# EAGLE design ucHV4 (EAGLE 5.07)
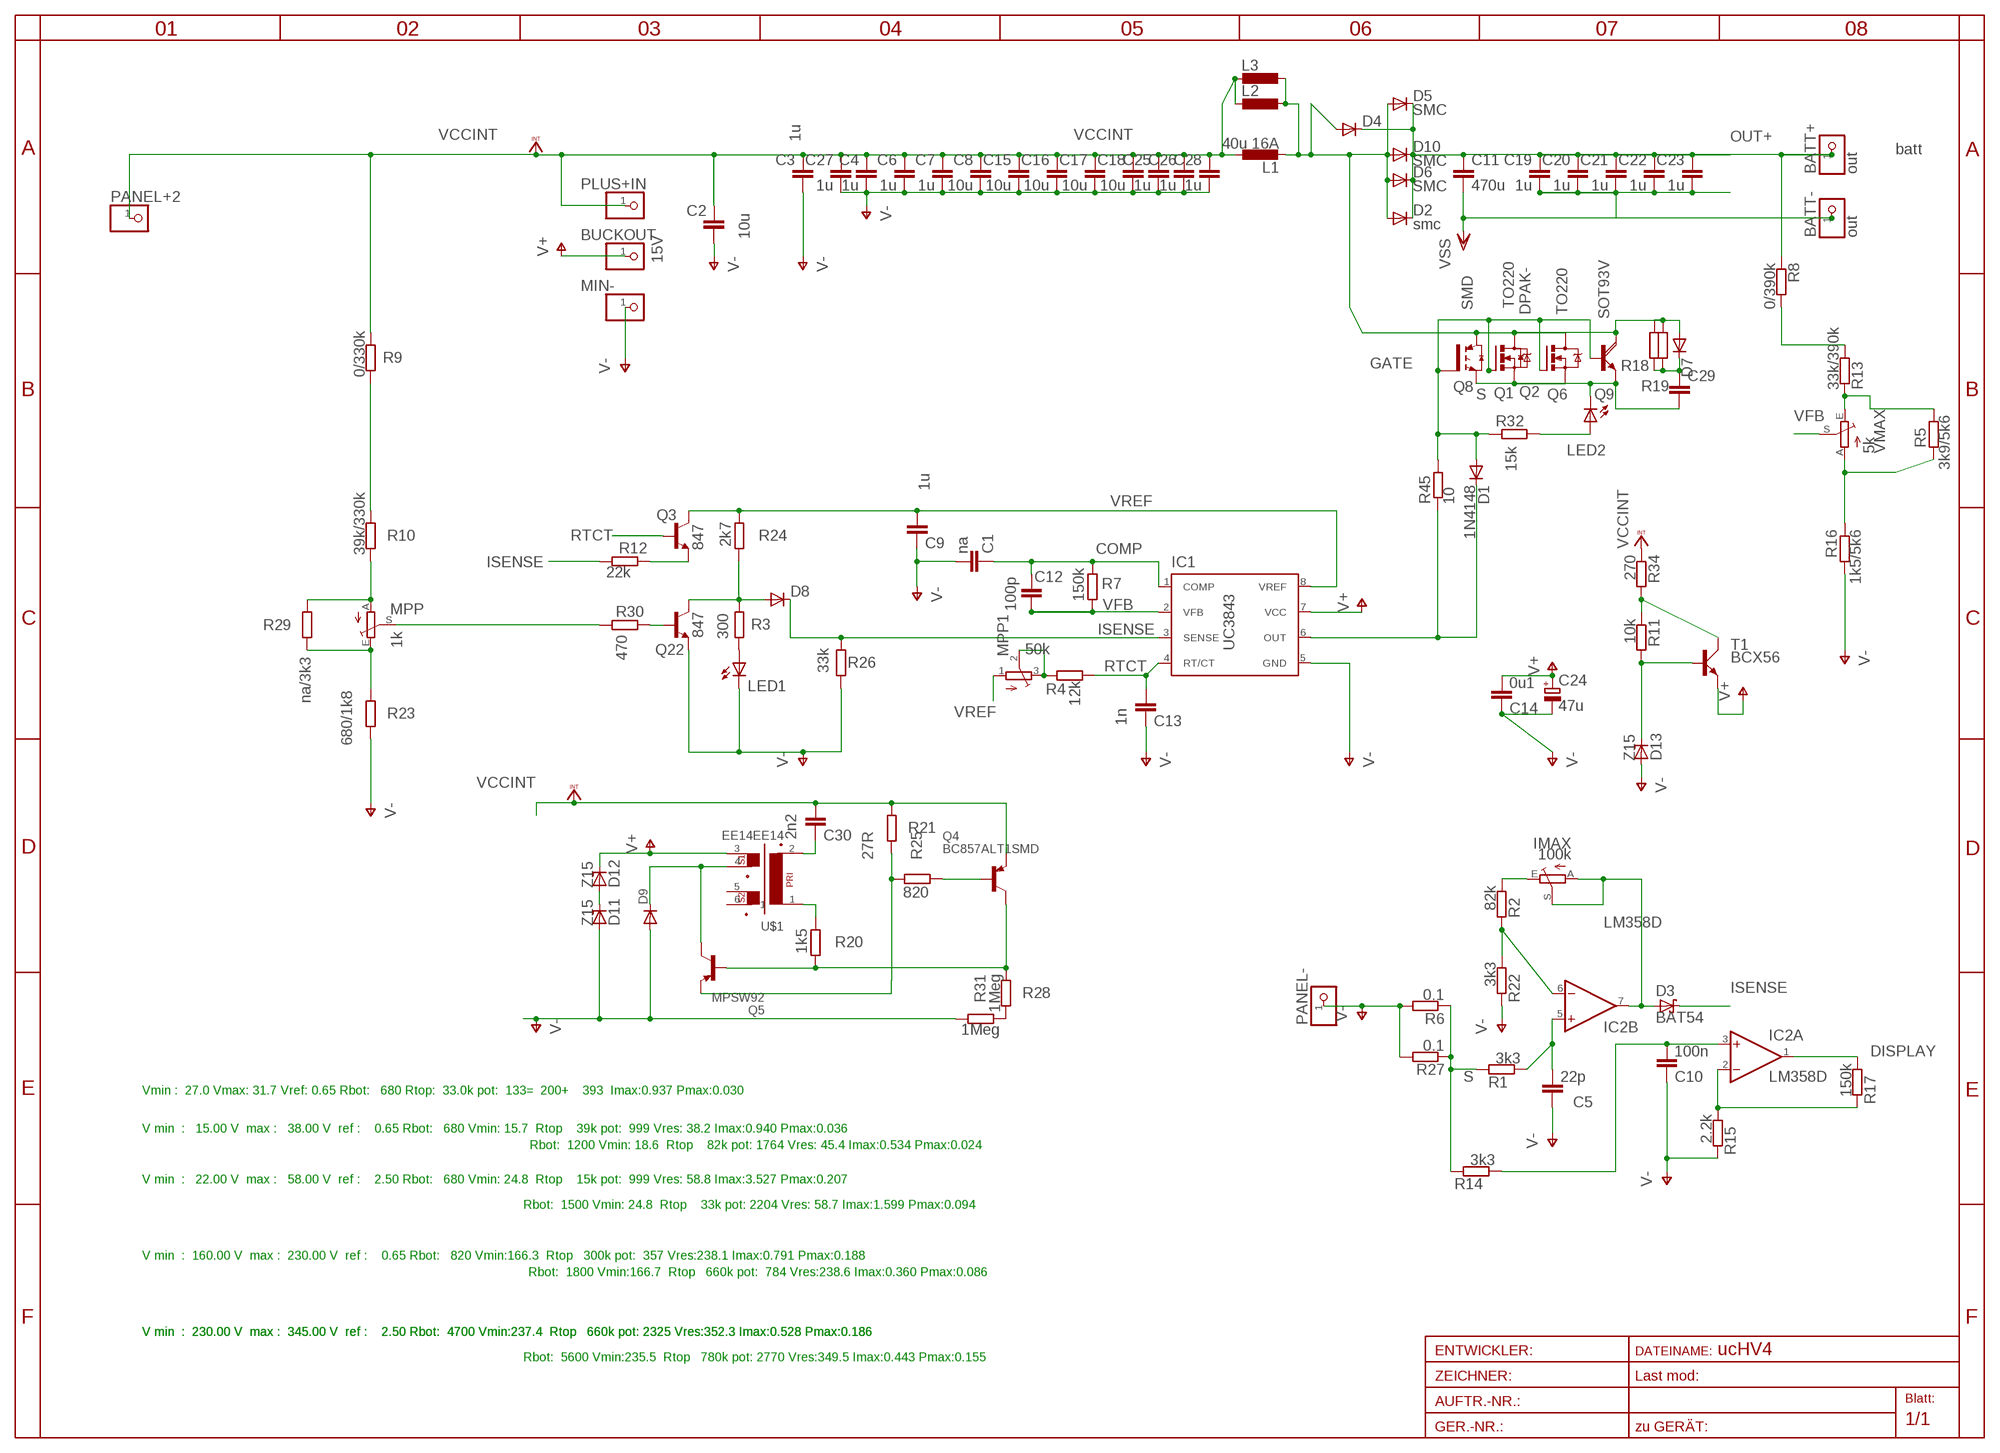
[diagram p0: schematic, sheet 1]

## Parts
BATT+  out  PINHD-1X12MM2  [1X2MM2]
BATT-  out  PINHD-1X12MM2  [1X2MM2]
BUCKOUT  15V  PINHD-1X11MM0  [1X1MM0]
C1  na  C-EUC0805  [C0805]
C2  10u  C-EUC058MLCC  [C058-020X040]
C3  1u  C-EUC058MLCC  [C058-020X040]
C4  1u  C-EUC058MLCC  [C058-020X040]
C5  22p  C-EUC0805  [C0805]
C6  1u  C-EUC058MLCC  [C058-020X040]
C7  1u  C-EUC058MLCC  [C058-020X040]
C8  10u  C-EUC058MLCC  [C058-020X040]
C9  1u  C-EUC1206  [C1206]
C10  100n  C-EUC1206  [C1206]
C11  470u  C-EU075-052X106  [C075-052X106]
C12  100p  C-EUC0805  [C0805]
C13  1n  C-EUC0805  [C0805]
C14  0u1  C-EUC1206  [C1206]
C15  10u  C-EUC058MLCC  [C058-020X040]
C16  10u  C-EUC058MLCC  [C058-020X040]
C17  10u  C-EUC058MLCC  [C058-020X040]
C18  10u  C-EUC058MLCC  [C058-020X040]
C19  1u  C-EUC1206  [C1206]
C20  1u  C-EUC1206  [C1206]
C21  1u  C-EUC1206  [C1206]
C22  1u  C-EUC1206  [C1206]
C23  1u  C-EUC1206  [C1206]
C24  47u  CPOL-EUSANYO_SMD_C6  [SANYO-OSCON_SMD_C6]
C25  1u  C-EUC058MLCC  [C058-020X040]
C26  1u  C-EUC058MLCC  [C058-020X040]
C27  1u  C-EUC058MLCC  [C058-020X040]
C28  1u  C-EUC058MLCC  [C058-020X040]
C29  C-EU075-032X103  [C075-032X103]
C30  2n2  C-EUC0805  [C0805]
D1  1N4148  DIODE-MINIMELF  [MINIMELF]
D2  smc  DIODE-SMC  [SMC]
D3  BAT54  [SOT23]
D4  DIODE-TO220H  [TO220AC]
D5  SMC  DIODE-SMC  [SMC]
D6  SMC  DIODE-SMC  [SMC]
D7  DIODE-DO34-7  [DO34-7]
D8  DIODE-SOT23  [SOT23]
D9  DIODE-SMA-DO214  [SMA-DO214AC]
D10  SMC  DIODE-SMC  [SMC]
D11  Z15  ZENER-DIODESOD80C  [SOD80C]
D12  Z15  ZENER-DIODESOD80C  [SOD80C]
D13  Z15  ZENER-DIODESOD80C  [SOD80C]
IC1  UC3843  UC1843D8  [SO-08]
IC2  LM358D  [SO08]
IMAX  100k  TRIM_EU-S64W  [S64W]
L1  40u 16A  L-EURNG  [RING]
L2  L-EU22U  [22U]
L3  L-EU22U  [22U]
LED1  LEDCHIPLED_1206  [CHIPLED_1206]
LED2  LEDCHIPLED_1206  [CHIPLED_1206]
MIN-  PINHD-1X11MM0  [1X1MM0]
MPP  1k  TRIM_EU-S64W  [S64W]
MPP1  50k  TRIM_EU-3223G  [3223G]
PANEL+2  PINHD-1X11MM6  [1X1MM8]
PANEL-  PINHD-1X12MM2  [1X2MM2]
PLUS+IN  PINHD-1X11MM0  [1X1MM0]
Q1  TO220  IRF740220  [TO220BV]
Q2  DPAK-  N-HEXFET_DPAK-  [TO252]
Q3  847  BC847ASMD  [SOT23]
Q4  BC857ALT1SMD  [SOT23-BEC]
Q5  MPSW92  [TO92-CBE]
Q6  TO220  IRF740220  [TO220BV]
Q8  SMD  IRG4BC15UD-S  [D2PACK]
Q9  SOT93V  TIP142SOT93V  [SOT93V]
Q22  847  BC847ASMD  [SOT23]
R1  3k3  R-EU_R0805  [R0805]
R2  82k  R-EU_R0805  [R0805]
R3  300  R-EU_R0805  [R0805]
R4  12k  R-EU_R0805  [R0805]
R5  3k9/5k6  R-EU_R0805  [R0805]
R6  0.1  R-EU_0207/10  [0207/10]
R7  150k  R-EU_R0805  [R0805]
R8  0/390k  R-EU_R1206  [R1206]
R9  0/330k  R-EU_R1206  [R1206]
R10  39k/330k  R-EU_R1206  [R1206]
R11  10k  R-EU_R1206  [R1206]
R12  22k  R-EU_0204/7  [0204/7]
R13  33k/390k  R-EU_R1206  [R1206]
R14  3k3  R-EU_R0805  [R0805]
R15  2.2k  R-EU_R1206  [R1206]
R16  1k5/5k6  R-EU_R0805  [R0805]
R17  150k  R-EU_R0805  [R0805]
R18  R-EU_0204/7  [0204/7]
R19  R-EU_0204/7  [0204/7]
R20  1k5  R-EU_R0805  [R0805]
R21  27R  R-EU_R0805  [R0805]
R22  3k3  R-EU_R0805  [R0805]
R23  680/1k8  R-EU_R0805  [R0805]
R24  2k7  R-EU_R0805  [R0805]
R25  820  R-EU_R0805  [R0805]
R26  33k  R-EU_R0805  [R0805]
R27  0.1  R-EU_R3216  [R3216]
R28  1Meg  R-EU_R1206  [R1206]
R29  na/3k3  R-EU_R1203  [R1203]
R30  470  R-EU_R0805  [R0805]
R31  1Meg  R-EU_R1206  [R1206]
R32  15k  R-EU_R0805  [R0805]
R34  270  R-EU_0617/17  [0617/17]
R45  10  R-EU_R0805  [R0805]
T1  BCX56  [SOT223]
U$1  EE14EE14  [EE14]
VMAX  5k  TRIM_EU-S64W  [S64W]

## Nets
COMP: C1.1 C12.2 IC1.1(COMP) R7.1
DISPLAY: IC2.1(A:OUT) R17.1
DQ18: D2.A D4.A D5.A D6.A D7.A D10.A L1.2 L2.1 L3.1 Q1.D Q2.3(D) Q6.D Q8.2(C) Q9.C R18.2 R19.2
GATE: D1.A Q1.G Q2.1(G) Q6.G Q8.1(G) Q9.B R32.1 R45.2
ISENSE: D3.3(C) D8.3(C) IC1.3(SENSE) R12.1 R26.1
N$1: C5.2 IC2.5(B:+IN) R1.1
N$2: IMAX.E R2.1
N$3: Q22.1(B) R30.1
N$4: LED1.A R3.2
N$5: LED2.A R32.2
N$6: R8.2 R13.2
N$7: D13.C R11.2 T1.1(B)
N$8: C30.1 U$1.2
N$9: Q3.2(E) R12.2
N$10: C10.2 IC2.3(A:+IN) R14.1
N$11: IC2.2(A:-IN) R15.1 R17.2
N$12: R20.1 U$1.1
N$13: MPP1.2(S) MPP1.3(E) R4.2
N$14: Q5.E R21.1 R25.1
N$15: Q4.B R25.2
N$16: D9.K(C) Q5.C U$1.4
N$17: Q4.C Q5.B R20.2 R28.2
N$19: R28.1 R31.1
N$21: R5.2 R16.1 VMAX.A
N$22: D3.1(A) IC2.7(B:OUT) IMAX.A IMAX.S
N$23: R11.1 R34.2 T1.2(C)
N$25: D1.C IC1.6(OUT) R45.1
N$26: D11.C D12.A
N$27: IC2.6(B:-IN) R2.2 R22.1
N$30: R9.1 R10.2
N$32: MPP.A R10.1 R29.1
N$34: MPP.E R23.2 R29.2
N$37: R5.1 R13.1 VMAX.E
N$71: D8.1(A) Q22.3(C) R3.1 R24.2
OUT+: BATT+.1 C11.1 C19.1 C20.1 C21.1 C22.1 C23.1 D2.C D4.C D5.C D6.C D10.C R8.1
PRB1: MPP.S R30.2
RTCT: C13.2 IC1.4(RT/CT) Q3.1(B) R4.1
S: C29.2 LED2.C Q1.S Q2.2(S) Q6.S Q8.3(E) Q9.E R1.2 R6.1 R14.2 R27.1
SNUB: C29.1 D7.C R18.1 R19.1
V+: BUCKOUT.1 C14.2 C24.+ D12.C IC1.7(VCC) T1.3(E) U$1.3
V-: BATT-.1 C1.2 C2.2 C3.2 C4.2 C5.1 C6.2 C7.2 C8.2 C9.1 C10.1 C11.2 C13.1 C14.1 C15.2 C16.2 C17.2 C18.2 C19.2 C20.2 C21.2 C22.2 C23.2 C24.- C25.2 C26.2 C27.2 C28.2 D9.A D11.A D13.A IC1.5(GND) LED1.C MIN-.1 PANEL-.1 Q22.2(E) R6.2 R15.2 R16.2 R22.2 R23.1 R26.2 R27.2 R31.2 ; supply symbol labelled VSS
VCCINT: C2.1 C3.1 C4.1 C6.1 C7.1 C8.1 C15.1 C16.1 C17.1 C18.1 C25.1 C26.1 C27.1 C28.1 C30.2 L1.1 L2.2 L3.2 PANEL+2.1 PLUS+IN.1 Q4.E R9.2 R21.2 R34.1
VFB: C12.1 IC1.2(VFB) R7.2 VMAX.S
VREF: C9.2 IC1.8(VREF) MPP1.1(A) Q3.3(C) R24.1
Unconnected: U$1.5 U$1.6

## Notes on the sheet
- batt
- Vmin :  27.0 Vmax: 31.7 Vref: 0.65 Rbot:   680 Rtop:  33.0k pot:  133=  200+    393  Imax:0.937 Pmax:0.030
- V min  :   15.00 V  max :   38.00 V  ref :    0.65 Rbot:   680 Vmin: 15.7  Rtop    39k pot:  999 Vres: 38.2 Imax:0.940 Pmax:0.036
- Rbot:  1200 Vmin: 18.6  Rtop    82k pot: 1764 Vres: 45.4 Imax:0.534 Pmax:0.024
- V min  :   22.00 V  max :   58.00 V  ref :    2.50 Rbot:   680 Vmin: 24.8  Rtop    15k pot:  999 Vres: 58.8 Imax:3.527 Pmax:0.207
- Rbot:  1500 Vmin: 24.8  Rtop    33k pot: 2204 Vres: 58.7 Imax:1.599 Pmax:0.094
- V min  :  160.00 V  max :  230.00 V  ref :    0.65 Rbot:   820 Vmin:166.3  Rtop   300k pot:  357 Vres:238.1 Imax:0.791 Pmax:0.188
- Rbot:  1800 Vmin:166.7  Rtop   660k pot:  784 Vres:238.6 Imax:0.360 Pmax:0.086
- V min  :  230.00 V  max :  345.00 V  ref :    2.50 Rbot:  4700 Vmin:237.4  Rtop   660k pot: 2325 Vres:352.3 Imax:0.528 Pmax:0.186 | V min  :  230.00 V  max :  345.00 V  ref :    2.50 Rbot:  4700 Vmin:237.4  Rtop   660k pot: 2325 Vres:352.3 Imax:0.528 Pmax:0.186
- Rbot:  5600 Vmin:235.5  Rtop   780k pot: 2770 Vres:349.5 Imax:0.443 Pmax:0.155

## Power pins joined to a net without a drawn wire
V+: IC2.8(P:V+)
V-: IC2.4(P:V-)

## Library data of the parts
BATT+ BATT- BUCKOUT MIN- PANEL+2 PANEL- PLUS+IN = pinhead:PINHD-1X1: PIN HEADER
C1-C23 C25-C30 = rcl:C-EU: CAPACITOR, European symbol
C24 = rcl:CPOL-EU: POLARIZED CAPACITOR, European symbol
D1 D2 D4-D10 = diode:DIODE-: DIODE
D3 = diode:BAT54: Schottky Diodes
D11-D13 = diode:ZENER-DIODE: Z-Diode
IC1 = texas:UC1843D8: PULSE WIDTH MODULATOR
IC2 = linear:LM358: OP AMP also LM158; LM258; LM2904 Source: http://cache.national.com/ds/LM/LM158.pdf
IMAX MPP MPP1 VMAX = pot:TRIM_EU-: POTENTIOMETER
L1-L3 = rcl:L-EU: INDUCTOR, European symbol
LED1 LED2 = led:LED: LED
Q1 Q6 = transistor-power:IRF740: N-CHANNEL MOS FET
Q2 = transistor-power:N-HEXFET_?-*: HEXFET® Power MOSFET
Q3 Q22 = transistor-npn:BC847*: NPN Transistor
Q4 = transistor-pnp:BC857*: PNP Transistror
Q5 = transistor-pnp:MPSW92*: PNP Transistror
Q8 = transistor-power:IRG4BC15UD-: INSULATED GATE BIPOLAR TRANSISTOR WITH ULTRAFAST SOFT RECOVERY DIODE
Q9 = transistor-power:TIP142: NPN DARLINGTON TRANSISTOR
R1-R10 R12-R31 R34 = rcl:R-EU_: RESISTOR, European symbol
R11 R32 R45 = rcl-2:R-EU_: RESISTOR, European symbol
T1 = transistor-power:BCX56
U$1 = trafo:EE14

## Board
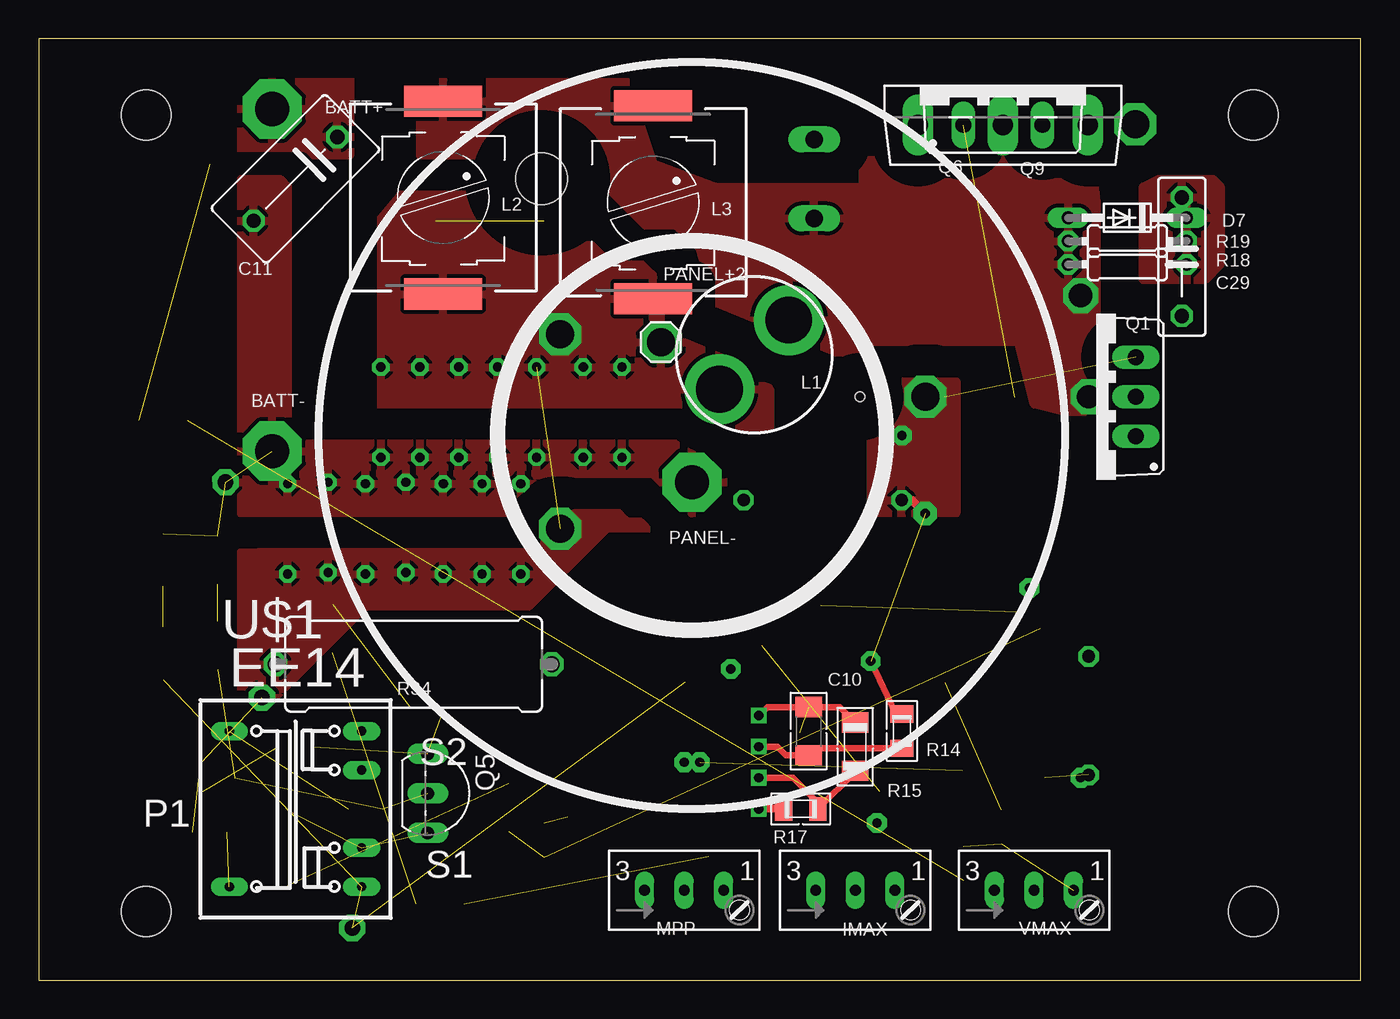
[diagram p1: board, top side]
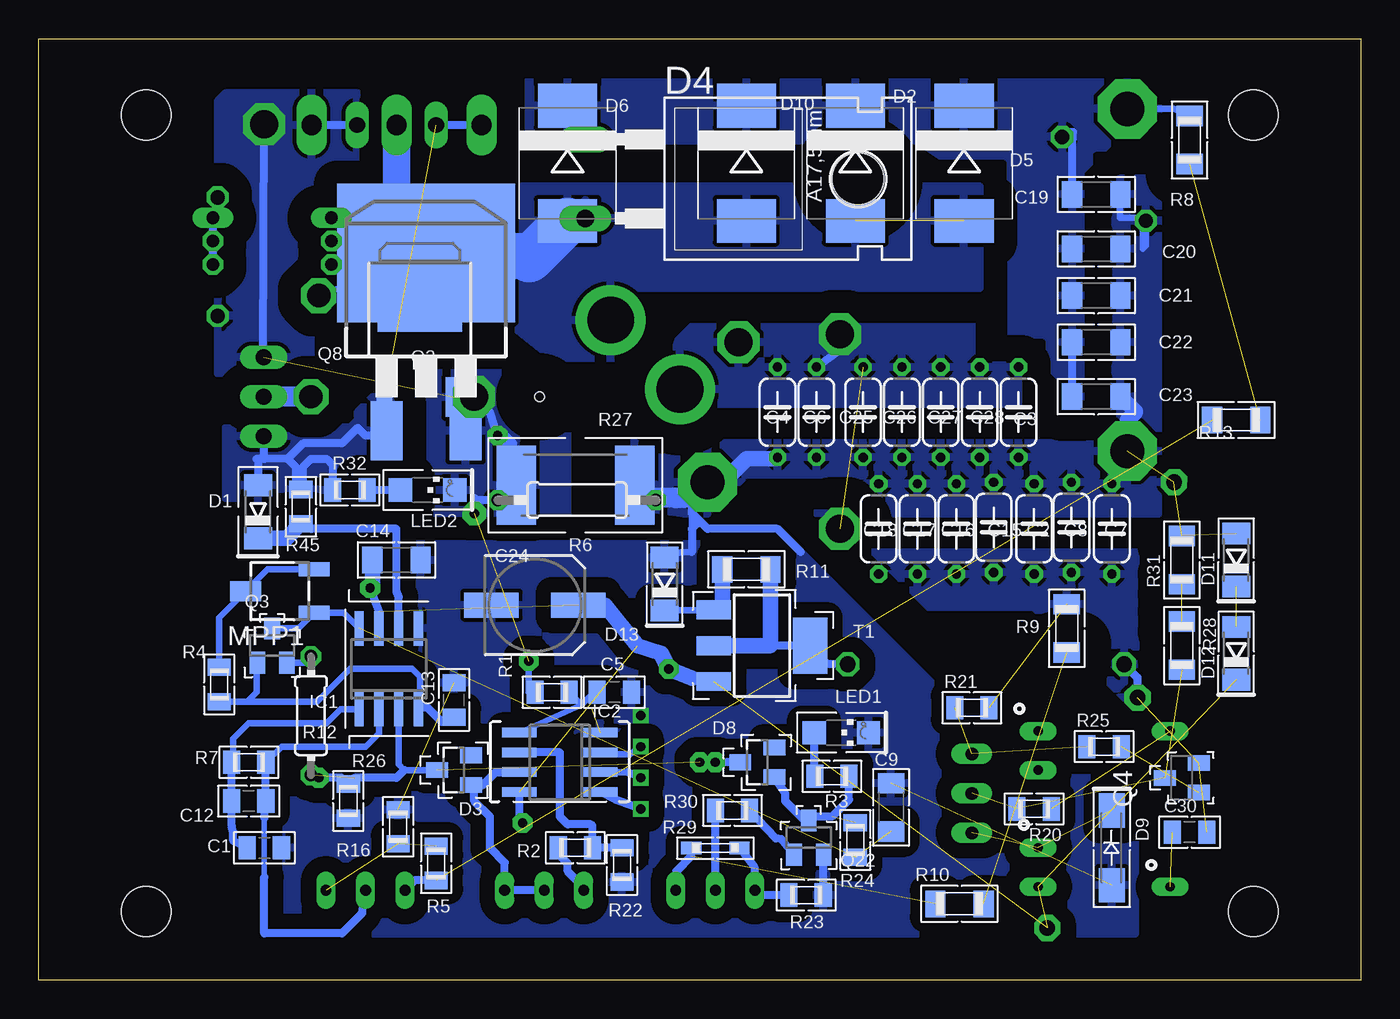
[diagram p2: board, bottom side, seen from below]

Size 85 x 60.5 mm. Coordinates in mm from the lower left corner, seen from the top.
Outline: 0,0 85,0 85,60.5 0,60.5 0,0
Copper layers (1*16): Top 0.035mm / dielectric 1.5mm / Bottom 0.035mm
Design rules "default *": minimum track width 10mil, minimum drill 0.5mm, track to track 8mil, track to pad 8mil, pad to pad 8mil, via to via 8mil, smd to smd 8mil, copper to edge 2.5mm, drill to drill 8mil, minimum pad ring 10mil, minimum via ring 8mil, stop-mask expansion 4mil, vias tented up to drill 0mil, thermal gap 10mil
Holes 3.2 mm at 6.9,55.6 6.9,4.4 78.1,4.4 78.1,55.6
Holes 0.6 mm at 52.8,37.5

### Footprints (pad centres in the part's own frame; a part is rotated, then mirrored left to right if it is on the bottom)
1X2MM2 = drill 2.2 pad 3.81 octagon: 1 0,0
1X1MM0 = drill 1 pad 1.676 octagon: 1 0,0
C0805 = smd 1.1 x 1.5: 1 -1.1,0; 2 1.1,0
C058-020X040 = drill 0.6 octagon: 1 -2.9,0; 2 2.9,0
C1206 = smd 1.3 x 1.7: 1 -1.55,0; 2 1.55,0
C075-052X106 = drill 0.914 octagon: 1 -3.81,0; 2 3.81,0
SANYO-OSCON_SMD_C6 = smd 3.5 x 1.6: + 2.8,0; - -2.8,0
C075-032X103 = drill 0.914 octagon: 1 -3.81,0; 2 3.81,0
MINIMELF = smd 1.4 x 1.8: A 1.7,0; C -1.7,0
SMC = smd 2.8 x 3.8: A 3.7,0; C -3.7,0
SOT23 = smd 1 x 1.4: 1 -0.95,-1.1; 2 0.95,-1.1; 3 0,1.1
TO220AC = drill 1.118 long: A 2.54,-6.35; C -2.54,-6.35 | hole 3.302: 0,11.176
DO34-7 = drill 0.813 long: A 3.81,0; C -3.81,0
SMA-DO214AC = smd 2.2 x 1.7: A 2.4,0; K -2.4,0
SOD80C = smd 1.4 x 1.8: A 1.7,0; C -1.7,0
SO-08 = smd 0.6 x 2.2: 1 -1.905,-2.6; 2 -0.635,-2.6; 3 0.635,-2.6; 4 1.905,-2.6; 5 1.905,2.6; 6 0.635,2.6; 7 -0.635,2.6; 8 -1.905,2.6
SO08 = smd 0.6 x 2.2: 1 -1.905,-2.6; 2 -0.635,-2.6; 3 0.635,-2.6; 4 1.905,-2.6; 5 1.905,2.6; 6 0.635,2.6; 7 -0.635,2.6; 8 -1.905,2.6
S64W = drill 0.7 long: A 2.54,1.27; E -2.54,1.27; S 0,1.27
RING = drill 3 pad 4 round: 1 -3.15,0; 2 3.15,0
22U = smd 5 x 2: 1 0,6.2; 2 0,-6.2
CHIPLED_1206 = smd 1.5 x 1.5: A 0,-1.75; C 0,1.75
3223G = smd 2 x 0.9: 1 -2.2,1.4; 3 -2.2,-1.4 | smd 2 x 1.3: 2 2.2,0
1X1MM8 = drill 1.8 pad 2.54 octagon: 1 0,0
TO220BV = drill 1.016 long: D 0,-2.54; G -2.54,-2.54; S 2.54,-2.54
TO252 = smd 1 x 1.6: 1 -2.28,-3.53 | smd 1.27 x 2.54: 2 2.28,-3.53 | smd 5.4 x 6.2: 3 0,3.77
SOT23-BEC = smd 1 x 1.4: B -0.95,-1.1; C 0,1.1; E 0.95,-1.1
TO92-CBE = drill 0.813 long: B 0,0; C 2.54,0; E -2.54,0
D2PACK = smd 2.083 x 3.81: 1 -2.54,-8.89; 3 2.54,-8.89 | smd 11.43 x 8.89: 2 0,2.54
SOT93V = drill 1.3 pad 1.676 long: B -5.461,-2.54; C 0,-2.54; E 5.461,-2.54
R0805 = smd 1.1 x 1.5: 1 -1.1,0; 2 1.1,0
0207/10 = drill 0.8 octagon: 1 -5.08,0; 2 5.08,0
R1206 = smd 1.3 x 1.7: 1 -1.55,0; 2 1.55,0
0204/7 = drill 0.813 octagon: 1 -3.81,0; 2 3.81,0
R3216 = smd 2.54 x 5.08: 1 -3.81,0; 2 3.81,0
R1203 = smd 1.3 x 0.8: 1 -1.55,0; 2 1.55,0
0617/17 = drill 1.016 octagon: 1 -8.89,0; 2 8.89,0
SOT223 = smd 1.219 x 2.235: 1 -2.311,-3.099; 2 0,-3.099; 3 2.311,-3.099 | smd 3.6 x 2.2: 4 0,3.099
EE14 = drill 0.6 pad 1.2 long: 1 4.25,-5; 2 4.25,5; 3 -4.25,5; 4 -4.25,2.5; 5 -4.25,-2.5; 6 -4.25,-5

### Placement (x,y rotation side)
BATT+  15,56 0 top
BATT-  15,34 0 top
BUCKOUT  20.16,3.34 90 top
C1  70.5,8.5 0 bottom
C2  21,29 90 bottom
C3  22,36.5 270 bottom
C4  37.5,36.5 270 bottom
C5  48,18.5 180 bottom
C6  35,36.5 270 bottom
C7  16,29 90 bottom
C8  18.6,29.1 90 bottom
C9  30.2,11.1 270 bottom
C10  49.5,16 270 top
C11  16.5,51.5 225 top
C12  71.5,11.5 180 bottom
C13  58.3,18 270 bottom
C14  62,27 180 bottom
C15  23.6,29.1 90 bottom
C16  26,29 90 bottom
C17  28.5,29 90 bottom
C18  31,29 90 bottom
C19  17,50.5 0 bottom
C20  17,47 0 bottom
C21  17,44 0 bottom
C22  17,41 0 bottom
C23  17,37.5 0 bottom
C24  53.1,24.1 0 bottom
C25  32,36.5 270 bottom
C26  29.5,36.5 270 bottom
C27  27,36.5 270 bottom
C28  24.5,36.5 270 bottom
C29  73.5,46.5 270 top
C30  11,9.5 0 bottom
D1  70.9,30.1 90 bottom
D2  32.5,52.5 270 bottom
D3  58.3,13.5 90 bottom
D4  43.5,51.5 270 bottom
D5  25.5,52.5 270 bottom
D6  51,52.5 270 bottom
D7  70,49 180 top
D8  38.8,14 90 bottom
D9  16,8.5 270 bottom
D10  39.5,52.5 270 bottom
D11  8,27 90 bottom
D12  8,21 90 bottom
D13  44.76,25.46 90 bottom
IC1  62.5,20 0 bottom
IC2  51.5,14 90 bottom
IMAX  52.5,4.5 0 top
L1  46,40.2 45 top
L2  26,50.3 0 top
L3  39.5,50 0 top
LED1  33.4,15.9 270 bottom
LED2  60,31.5 270 bottom
MIN-  12,32 315.7 top
MPP  41.5,4.5 0 top
MPP1  69.5,25 180 bottom
PANEL+2  40,41 0 top
PANEL-  42,32 90 top
PLUS+IN  14.34,18.16 90 top
Q1  68,37.5 90 top
Q2  60.5,41 0 bottom
Q3  70,21.5 0 bottom
Q4  11.5,13 90 bottom
Q5  25,12 270 top
Q6  62,57.5 0 top
Q8  60.1,44.2 0 bottom
Q9  62,57.5 0 top
Q22  35.49,9.16 0 bottom
R1  52,18.5 180 bottom
R2  50.5,8.5 0 bottom
R3  34,13.1 180 bottom
R4  73.4,19 90 bottom
R5  59.45,7.5 90 bottom
R6  50.4,30.84 0 bottom
R7  71.5,14 0 bottom
R8  11,54 270 bottom
R9  18.9,22.6 90 bottom
R10  25.8,4.9 0 bottom
R11  39.5,26.4 180 bottom
R12  67.5,17 90 bottom
R13  8,36 0 bottom
R14  55.5,16 90 top
R15  52.5,15 90 top
R16  61.9,9.85 90 bottom
R17  49,11 0 top
R18  70,46 180 top
R19  70,47.5 180 top
R20  21,11 180 bottom
R21  25,17.5 0 bottom
R22  47.5,7.4 270 bottom
R23  35.66,5.46 180 bottom
R24  32.5,9 90 bottom
R25  16.5,15 0 bottom
R26  65.1,11.5 270 bottom
R27  50.5,31.8 0 bottom
R28  11.5,21.5 270 bottom
R29  41.5,8.5 0 bottom
R30  40.4,10.9 180 bottom
R31  11.5,27 90 bottom
R32  65,31.5 0 bottom
R34  24.1,20.3 0 top
R45  68.15,30.43 90 bottom
T1  38.5,21.5 270 bottom
U$1  16.5,11 180 top
VMAX  64,4.5 0 top

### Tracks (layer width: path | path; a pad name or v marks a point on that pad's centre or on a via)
COMP
  Bottom 0.406: IC1.1 65.6,17.4 66.5,16.5 71.5,16.5 72.5,15.5 72.5,14.1 R7.1
  Bottom 0.5: C1.1 72.5,8.95 72.5,9.5 72.6,9.9 C12.2 R7.1
DISPLAY  (via drill 0.6)
  Top 0.5: R17.1 v46.3,11
  Bottom 0.5: IC2.1 47.91,11.6 v46.3,11
DQ18  (via drill 1.5 pad 1.2)  (1 unrouted)
  Bottom 0.406: v67,44 61.4,46 61.4,46.89
  Bottom 0.5: Q2.3 60.5,45.1 61.4,46
  Bottom 1.27: v67.5,37.5 Q1.D
  Bottom 1.778: 62,47.04 Q9.C
  Bottom 2.54: Q8.2 61.4,46.89 62,47.04
  Bottom 3: Q8.2 53.54,46.54 53.47,46.34 D6.A
  pour Bottom (isolate 1.5, rank 2): 24.5,51 55.5,51 54.5,42 52,40 47,40 47,44.5 24.5,44.5
  pour Top (isolate 2): 53,54.5 67.5,54.5 68,50 68,37 67.5,36.5 66,36.5 64,37 63,41 53,41
  pour Top (isolate 1.5, rank 2): 54.5,51 54.5,42 52,40 43.5,43.5 42.5,47 41,48.5 39,48.5 34.5,53 24.5,53 24.5,58.5 37.5,58.5 39.5,52.5 43.5,51
GATE  (1 unrouted)
  Bottom 0.5: Q8.1 62.64,37.33 Q2.1 62.78,35.22 63,35 64,35 64.5,35.5 65.5,34.5 68,34.5 69,33.5 | R32.1 66.1,33.1 66.5,33.5 67.5,33.5 68,33 68,31.68 R45.2 68.03,31.53 | D1.A 70.9,33.4 71,33.5 70.5,33.5 | 69,33.5 68.5,33 68.5,32 68.03,31.53 | 68.03,31.53 68,31.5 | 69,33.5 70.5,33.5 | 70.5,33.5 70.5,35 | Q9.B Q6.G
  pour Bottom (isolate 1.5): 62.5,37.5 63.5,37.5 64.5,36.5 64.5,36 65,35.5 73,35.5 73,31 66,31 65.5,31.5 65.5,32 63.5,34 62,34 62,36.5
ISENSE  (via drill 0.6 pad 1.27)  (2 unrouted)
  Bottom 0.406: D3.3 61.5,13.5 61.87,13.87 IC1.3
  Bottom 0.5: D8.3 v41.5,14 v42.5,14 | v67,13 65.5,13 R26.1 64.7,13 62,13 61.5,13.5
N$1
  Bottom 0.406: 50.1,17.7 IC2.5 | 50.1,17.7 R1.1 | C5.2 49.3,18.5 50.1,17.7
N$2
  Bottom 0.5: IMAX.E 49.96,5.96 51,7 51,7.5 51.5,8 51.5,8.4 R2.1
N$3
  Bottom 0.5: Q22.1 37.26,9.06 37.6,9.1 R30.1
N$4
  Bottom 0.5: R3.2 LED1.A
N$5
  Bottom 0.5: LED2.A R32.2
N$6  (1 unrouted)
N$7
  Bottom 0.406: D13.C 40.84,23.76 41.02,23.77 T1.1
  Bottom 1: R11.2 41.05,23.8 41.02,23.77
N$8  (1 unrouted)
N$9
  Bottom 0.406: Q3.2 67.91,20.4 R12.2
N$10  (via drill 0.6)
  Top 0.406: v46.3,15 47.5,15 48.05,14.45 C10.2 49.95,14.9 R14.1
  Bottom 0.406: IC2.3 48.63,14.63 48.5,14.5 47,14.5 v46.3,15
N$11  (via drill 0.6)
  Top 0.406: v46.3,13 48.5,13 49,12.5 50.1,11.4 R17.2 52.5,13.4 R15.1
  Top 0.5: v46.3,13 46.5,13
  Bottom 0.406: 47.13,13.37 IC2.2
  Bottom 0.5: v46.3,13 47.13,13.37
N$12  (1 unrouted)
N$13
  Bottom 0.406: MPP1.3 70.3,26.4 MPP1.2 73.4,23.3 R4.2
N$14  (2 unrouted)
N$15  (1 unrouted)
N$16  (2 unrouted)
N$17  (3 unrouted)
N$19  (1 unrouted)
N$21  (2 unrouted)
N$22
  Bottom 0.5: IMAX.S IMAX.A 55.04,7.54 56,8.5 56,10.5 57,11.5 57,12.45 D3.1 56.85,12.5 56.5,12.5 55.63,13.37 IC2.7
N$23
  Bottom 0.5: R34.2 34.3,20.3 35.5,21.5 37.9,21.5 37.95,21.55
  Bottom 1: T1.2 38,21.5 37.95,21.55 R11.1
N$25
  Bottom 0.5: IC1.6 61.87,24.64 62,25 62,29 67.48,29 R45.1
  Bottom 1: D1.C 69.08,28.4 R45.1
N$26  (1 unrouted)
N$27
  Bottom 0.5: IC2.6 51.5,14.63 51.5,10.5 51,10 49.5,10 49.4,9.9 R2.2 R22.1
N$30  (1 unrouted)
N$32  (1 unrouted)
  Bottom 0.5: 44.04,6.04 MPP.A 44,5.81 44,7 43.05,7.95 R29.1
N$34
  Bottom 0.5: R23.2 38.77,5.46 MPP.E 38.96,7.21 R29.2
N$37  (1 unrouted)
  Bottom 0.5: 61.4,5.83 VMAX.E 60.83,6.4 R5.1
N$71  (1 unrouted)
  Bottom 0.5: R3.1 32.9,11.6 34,10.5 35.25,10.5 Q22.3 35.76,10.26 37,11.5 37,12 D8.1
OUT+
  Bottom 0.406: R8.1 11.05,55.55 12,56 12.5,56 BATT+.1
  Bottom 0.5: C23.1 C22.1 | C19.1 18.55,53.45 18.5,54.5 18.89,54.5 C11.1
  pour Bottom (isolate 1.5, rank 4): 13,55 13,59.5 53.5,59.5 53.5,54 28.5,54 22.5,50 22.5,41 arc46 18,36.5 18,52 15.5,54.5
  pour Top (isolate 1.5, rank 4): 13,53 13,58.5 20,58.5 20,53
PRB1
  Bottom 0.5: MPP.S R30.2
RTCT
  Bottom 0.406: IC1.4 60.5,17.5 60.5,19.5 61,20 65,20 67.1,17.9 R4.1 71.6,17.9 71,18.5 71,20.35 Q3.1
  Bottom 0.5: C13.2 59.1,16.6 60,17.5 60.49,17.5 IC1.4
S  (via drill 0.6 pad 1.27, 0.6 pad 1.5, 1.8 pad 2.54)  (2 unrouted)
  Top 0.406: R14.2 55.1,17.1 v53.5,20.5
  Top 0.5: R6.1 56.16,30.84 v57,30
  Bottom 0.406: R1.2 53.5,18.5 v53.5,20.5
  Bottom 0.5: Q6.S Q9.E | 57.11,35.11 Q8.3 57.56,36.81 Q2.2 | v57,37.5 56,36.5 v55.5,35 54.5,34.5 55,35 55,30.97 R6.1 56.84,30.84 57,31 | v70.5,55 70.58,40 Q1.S
  Bottom 1.27: R6.1 54.31,30.95 R27.1
  pour Bottom (isolate 1.5): 64.5,57 73,57 73.5,56.5 73.5,39 67.5,39 67.5,49 64.5,52
  pour Top: 54,38.5 59,38.5 59,36.5 59,30 53.5,30 53.5,35.5
  pour Bottom (isolate 1.5, rank 3): 51,39 60,39 60,30 51,30
SNUB
  Bottom 0.5: C29.1 73.5,49.31 D7.C R19.1 R18.1
  pour Top: 72,51.5 75.5,51.5 76,51 76,46 75,45 71,45 71,51
V+  (via drill 0.6 pad 1.27)  (5 unrouted)
  Bottom 0.406: T1.3 43,19.39 | 48.6,24.1 C24.+
  Bottom 0.5: IC1.7 63.13,23.66 v63.7,25.2 | IC2.8 54.1,10.4 v53.9,10.1
  Bottom 1: 43,19.39 v44.5,20 45,21 46.5,21.5 48.6,24.1 | C14.2 63.55,25.35 v63.7,25.2
V-  (via drill 0.6)  (6 unrouted)
  Top 0.406: v46.3,17 46.85,17.55 C10.1 51.5,17.55 R15.2
  Bottom 0.406: 43,29.7 43,27.5 43.71,27.5 D13.A | C11.2 13.81,47.19 14,47 14,49 15.5,49 15.5,50.45 C19.2
  Bottom 0.5: R23.1 34.5,5.5 34.5,5 34.54,5.97 Q22.2 | 43,31 43,30 42.5,29.5 | 42.5,29.5 42,29 37.5,29 36,27.5 | 43,27.5 43,29 42.5,29.5 | R6.2 43.66,30.84 43.5,31
  Bottom 1: PANEL-.1 41,32 39.5,33.5 37.6,33.5 C4.2 | BATT-.1 15,36 14.5,36.5 14.5,36.55 C23.2
  Bottom 1.27: 43,31 43.5,31 | 43.5,31 46.69,31 R27.2 | 43.5,31 44,30.95
  pour Bottom (isolate 1): 36.5,28 72.5,28 72.5,3 14.5,3 14.5,17.5 26,17.5
  pour Bottom (isolate 2): 13,51.5 15.5,51.5 16,51 16,34.5 47,34.5 47,30.5 43.5,30 42,30 39.5,32.5 32.5,32.5 30,30 13,30
  pour Top (isolate 2): 13,51.5 15.5,51.5 16,51 16,34.5 44,34.5 44,30.5 43.5,30 42,30 39.5,32.5 32.5,32.5 30,30 13,30
VCCINT  (via drill 1.8 pad 2.54)  (4 unrouted)
  Bottom 0.5: C6.1 33.6,40.4 v33.5,41.5 | 14.4,18.1 PLUS+IN.1 14.34,19.43 R34.1
  other vias: 33.5,29
  pour Bottom (isolate 2, rank 2): 13.5,28 30,28 33,31.5 40,31.5 40,29 36.5,29 31.5,24 21,24 15,18 14,18 13.5,18.5
  pour Bottom (isolate 2, rank 3): 25,42.5 42.5,42.5 47,38 47,35.5 39.5,35.5 39,36 22,36.5 22,39.5 25,39.5
  pour Top (isolate 2, rank 2): 13,27.5 30,28 33,31.5 40,31.5 40,29 36.5,29 31.5,24 21,24 15,18 13,18
  pour Top (isolate 2, rank 3): 24.5,52 34,52 47,38 47,35.5 39.5,35.5 39,36 22,36.5 22,49
VFB
  Bottom 0.35: 70.5,6.63 70.5,10.4
  Bottom 0.406: IC1.2 63.13,15.87 64,15 69.4,15 R7.2
  Bottom 0.5: VMAX.S 64.2,4.29 65.5,3 70.5,3 70.5,6.63 | 70.5,10.4 70.4,11.16 C12.1 R7.2
VREF  (2 unrouted)
  Bottom 0.406: Q3.3 68.3,22.6 MPP1.1 65.41,23.6 IC1.8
